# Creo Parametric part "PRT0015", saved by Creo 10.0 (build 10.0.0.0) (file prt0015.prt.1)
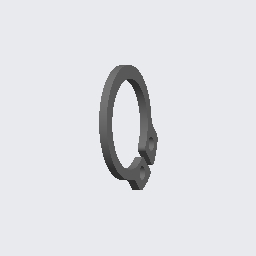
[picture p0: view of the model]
Units: millimeter Newton Second (mmNs); MM, TONNE, SECS

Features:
  1. coordinate system "61741200"
  2. imported feature "Import-ke ID 4"

Other named items: NOTE_0

Notes: 61741200

Surfaces: 16 cylinder, 6 plane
